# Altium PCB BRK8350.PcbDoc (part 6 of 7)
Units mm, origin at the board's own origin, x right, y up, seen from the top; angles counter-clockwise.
Board outline 240 x 150 mm, 8 copper layers (L1-TOP, L2-GND, L3-PWR, L4-SIG, L5-SIG, L6-PWR, L7-GND, L8-BOT), stack 1.465 mm thick; 277 components, 542 nets, 1814 pads, 2338 vias.
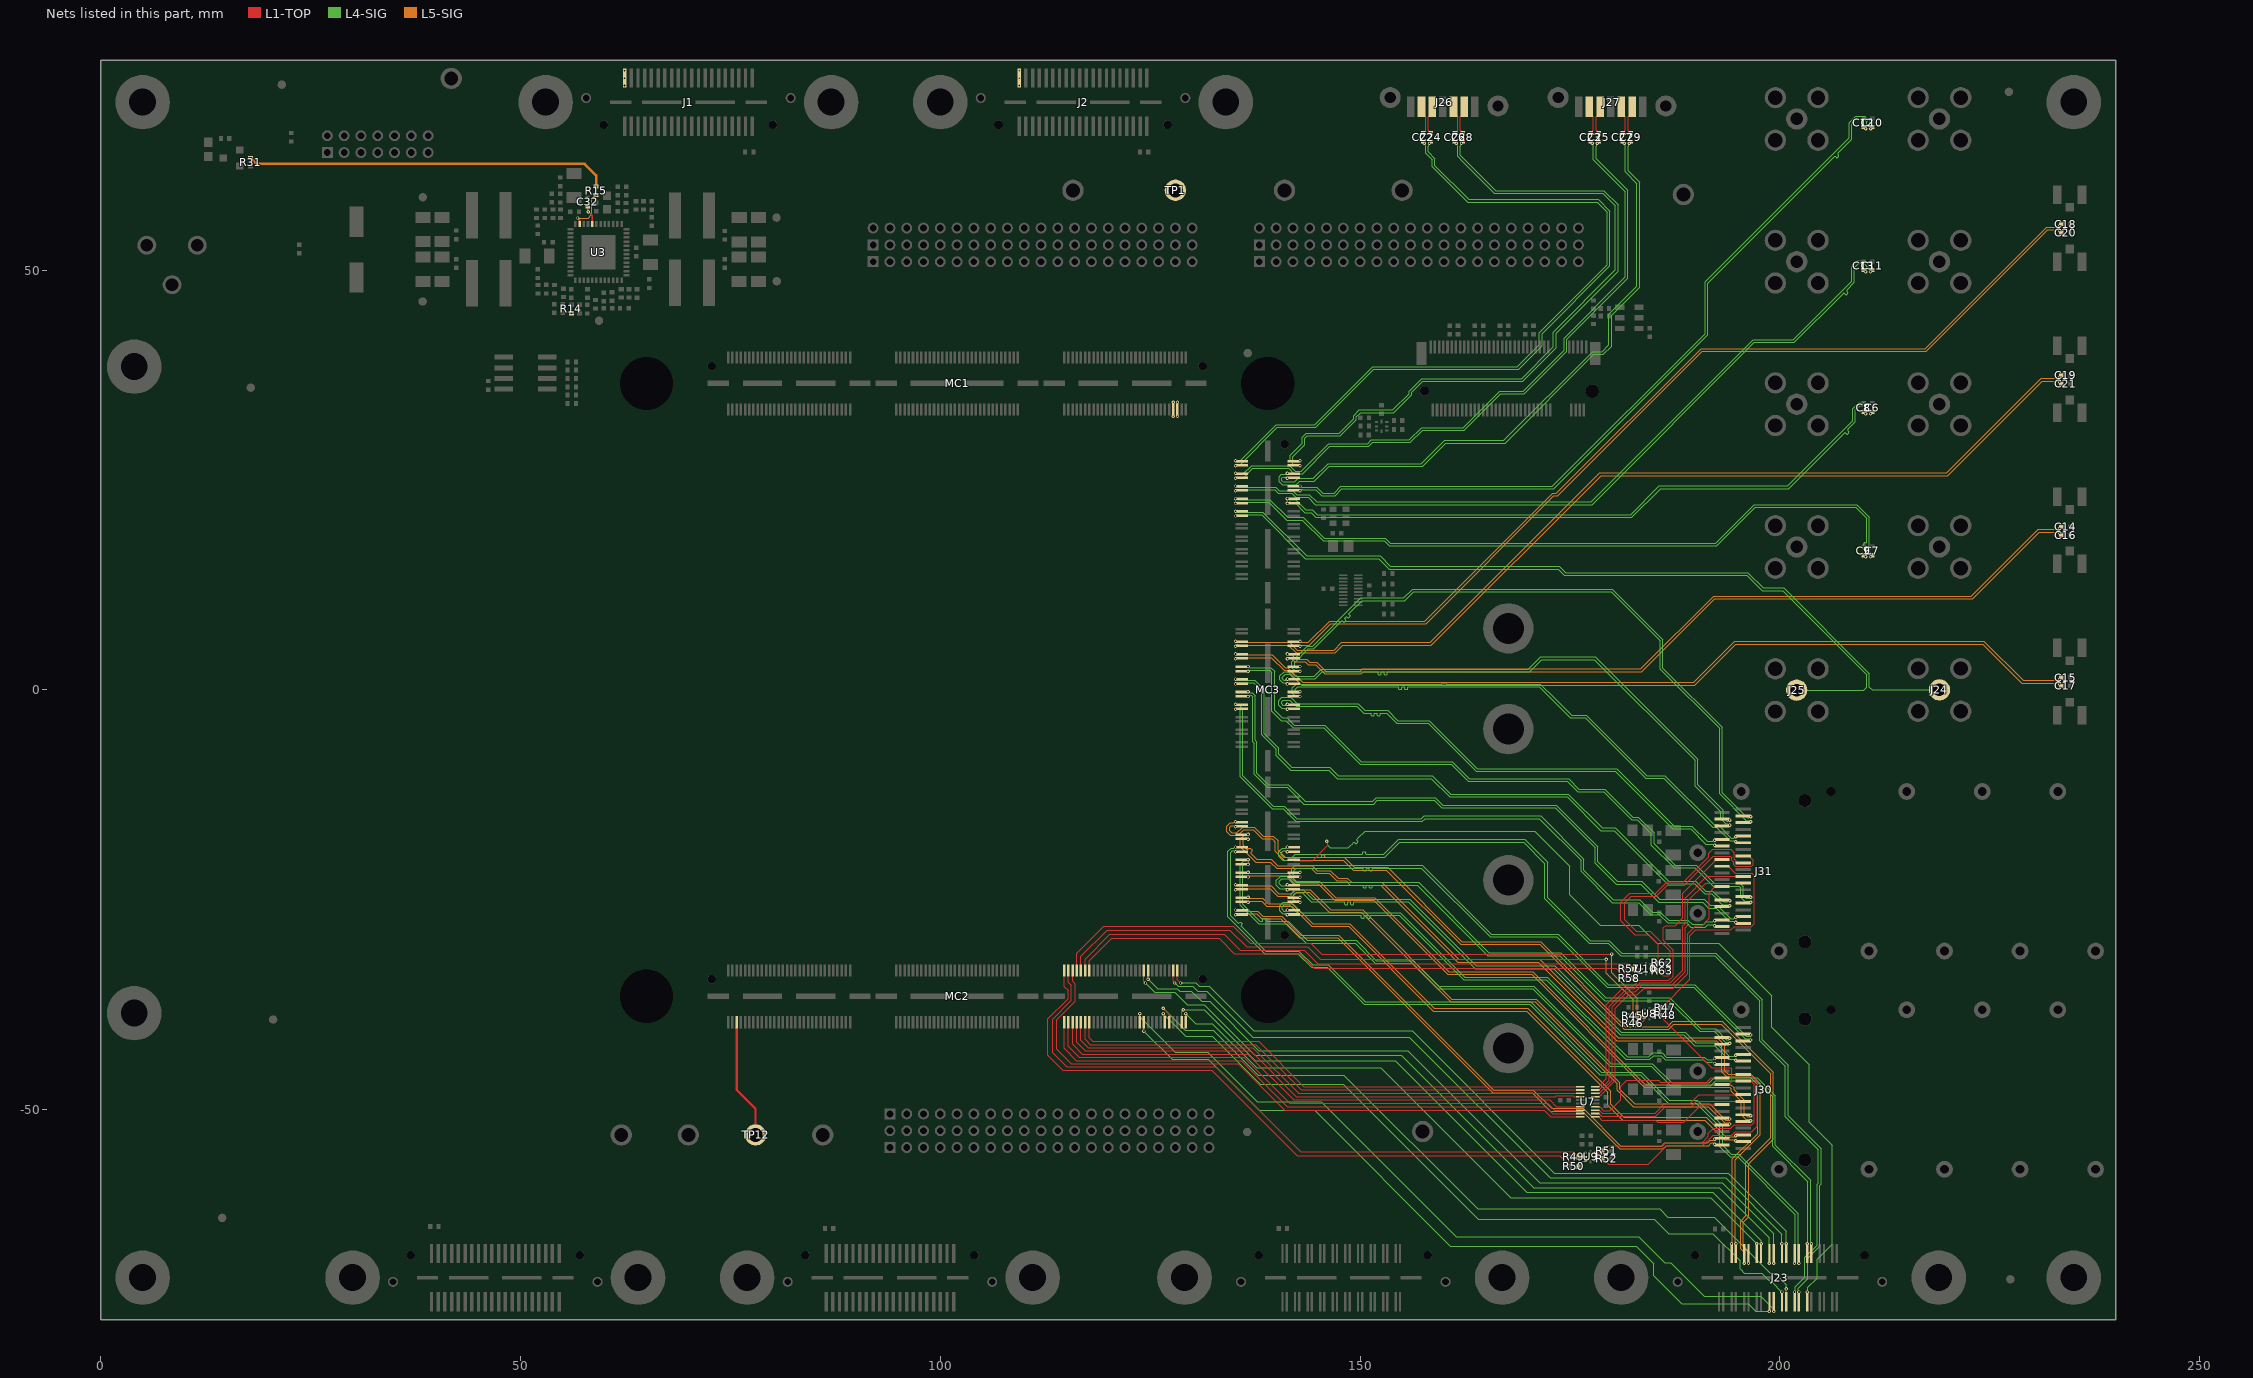
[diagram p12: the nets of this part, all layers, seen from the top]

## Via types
v1: diameter 0.406, hole 0.203, L1-TOP to L8-BOT, tented both sides, 2338 vias

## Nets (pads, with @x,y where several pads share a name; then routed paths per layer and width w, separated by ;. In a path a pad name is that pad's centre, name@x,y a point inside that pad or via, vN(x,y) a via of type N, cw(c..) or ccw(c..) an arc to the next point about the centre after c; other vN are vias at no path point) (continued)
PORTF_RX2P: J23.29 MC3.101 | length 110
  L1-TOP w0.107: MC3.101@142.09,-20.25 142.18,-20.34 144.333,-20.34 146.153,-18.52 146.153,-18.218 146.025,-18.09 v1(146.025,-18.009)
  L4-SIG w0.107: v1(146.025,-18.009) 146.025,-18.09 146.153,-18.218 146.153,-18.522 146.452,-18.821 148.59,-18.821 148.91,-18.501 149.038,-18.374 149.254,-18.157 149.331,-18.157 149.487,-18.313 149.563,-18.313 149.742,-18.134 149.742,-18.058 149.586,-17.902 149.586,-17.826 149.784,-17.628 150.597,-16.815 170.79,-16.815 174.955,-20.98 174.955,-24.405 178.582,-28.031 183.2,-28.031 185.318,-30.15 192.714,-30.15 199.019,-36.455 199.019,-40.163 203.515,-44.659 203.515,-51.517 206.223,-54.224 206.223,-65.994 204.429,-67.787 204.429,-70.05 203.34,-71.14 203.34,-71.534 203.237,-71.637 v1(203.237,-71.718)
PORTF_RX3N: J23.27 MC3.99 | length 109.2
  L4-SIG w0.107: v1(141.344,-19.288) 141.263,-19.288 141.135,-19.16 140.843,-19.16 140.614,-19.388 140.614,-19.66 140.894,-19.939 141.914,-19.939 142.262,-19.591 150.114,-19.591 150.24,-19.591 150.294,-19.537 150.294,-19.317 150.348,-19.263 150.601,-19.263 150.655,-19.317 150.655,-19.537 150.709,-19.591 150.901,-19.591 152.803,-19.591 154.579,-17.816 169.601,-17.816 172.329,-20.543 172.329,-24.759 177.44,-29.87 179.68,-29.87 181.153,-31.344 192.375,-31.344 197.917,-36.885 197.917,-41.661 200.965,-44.709 200.965,-50.703 204.894,-54.632 204.894,-58.86 204.739,-59.014 204.739,-66.253 203.291,-67.701 203.291,-70.114 202.16,-71.246 202.16,-71.534 202.263,-71.637 v1(202.263,-71.718)
PORTF_RX3P: J23.25 MC3.97 | length 109.2
  L4-SIG w0.107: v1(141.344,-18.711) 141.263,-18.711 141.135,-18.84 140.71,-18.84 140.294,-19.256 140.294,-19.792 140.761,-20.259 142.047,-20.259 142.395,-19.911 152.936,-19.911 154.711,-18.136 169.469,-18.136 172.009,-20.676 172.009,-24.892 177.307,-30.19 179.547,-30.19 181.02,-31.664 192.242,-31.664 197.597,-37.018 197.597,-41.793 200.645,-44.841 200.645,-50.836 204.574,-54.765 204.574,-58.727 204.419,-58.882 204.419,-66.121 202.971,-67.569 202.971,-69.982 201.84,-71.113 201.84,-71.534 201.737,-71.637 v1(201.737,-71.718)
PORTF_S0: J23.14 MC2.180 | length 80.4
  L1-TOP w0.114: MC2.180@129.25,-39.59 v1(129.25,-38.55)
  L4-SIG w0.117: v1(129.25,-38.55) 130.452,-39.751 132.41,-39.751 137.668,-45.009 152.457,-45.009 167.951,-60.503 191.762,-60.503 v1(197.237,-65.978)
PORTF_S1: J23.16 MC2.178 | length 82.2
  L1-TOP w0.114: MC2.178@128.75,-39.59 128.75,-38.276 v1(128.933,-38.093)
  L4-SIG w0.117: v1(128.933,-38.093) 131.412,-38.093 137.516,-44.196 154.178,-44.196 169.824,-59.842 191.972,-59.842 197.763,-65.633 v1(197.763,-65.978)
PORTF_S2: J23.17 MC2.160 | length 90.2
  L1-TOP w0.114: v1(124.25,-40.629) MC2.160@124.25,-39.59
  L4-SIG w0.117: v1(124.25,-40.629) 127.614,-43.993 131.902,-43.993 137.973,-50.063 144.577,-50.063 160.757,-66.243 182.883,-66.243 184.988,-68.349 184.988,-69.774 188.316,-73.101 196.201,-73.101 197.122,-74.023 v1(198.737,-74.023)
PORTF_S3: J23.18 MC2.159 | length 91.5
  L1-TOP w0.114: MC2.159@124.25,-33.41 124.25,-34.724 v1(124.433,-34.907)
  L4-SIG w0.117: v1(124.433,-34.907) 125.544,-36.017 127.914,-36.017 129.388,-37.49 131.445,-37.49 137.465,-43.51 154.915,-43.51 170.688,-59.284 192.785,-59.284 198.737,-65.236 v1(198.737,-68.283)
PORTF_S4: J23.19 MC2.158 | length 91.6
  L1-TOP w0.114: MC2.158@123.75,-39.59 v1(123.75,-38.55)
  L4-SIG w0.117: v1(123.75,-38.55) 123.75,-38.914 127.991,-43.155 131.851,-43.155 137.77,-49.073 145.39,-49.073 161.442,-65.126 183.185,-65.126 186.285,-68.226 186.996,-68.226 191.008,-72.238 197.745,-72.238 199.263,-73.755 v1(199.263,-74.023)
PORTF_S5: J23.20 MC2.161 | length 91.6
  L1-TOP w0.114: v1(124.75,-34.449) MC2.161@124.75,-33.41
  L4-SIG w0.117: v1(124.75,-34.449) 125.886,-35.585 128.232,-35.585 128.511,-35.865 129.87,-35.865 131.115,-37.109 132.105,-37.109 137.947,-42.951 155.651,-42.951 171.374,-58.674 193.14,-58.674 199.263,-64.796 v1(199.263,-68.283)
PORTF_S6: J23.21 MC2.170 | length 89.1
  L1-TOP w0.114: v1(126.563,-38.548) 126.75,-38.735 MC2.170@126.75,-39.59
  L4-SIG w0.117: v1(126.563,-38.548) 129.239,-41.224 132.385,-41.224 138.1,-46.939 147.98,-46.939 164.059,-63.017 185.014,-63.017 186.741,-64.745 191.999,-64.745 195.25,-67.996 195.25,-68.961 195.767,-69.478 197.809,-69.478 198.84,-70.509 199.029,-70.509 v1(200.237,-71.718)
PORTF_S7: J23.22 MC2.173 | length 87.4
  L1-TOP w0.114: MC2.173@127.75,-33.41 127.75,-34.724 v1(127.933,-34.907)
  L4-SIG w0.117: v1(127.933,-34.907) 128.333,-35.306 130.048,-35.306 130.645,-35.903 131.737,-35.903 137.185,-41.351 155.88,-41.351 172.618,-58.09 193.523,-58.09 200.237,-64.804 v1(200.237,-65.978)
PORTF_S8: J23.23 MC2.172 | length 91.8
  L1-TOP w0.114: v1(126.563,-37.922) 127.25,-38.609 MC2.172@127.25,-39.59 ; J23.23@200.75,-72.87 200.75,-71.359 v1(200.767,-71.342)
  L4-SIG w0.117: v1(126.563,-37.922) 129.154,-40.513 132.537,-40.513 137.897,-45.872 148.057,-45.872 164.008,-61.824 185.674,-61.824 186.639,-62.789 192.151,-62.789 198.84,-69.478 199.376,-69.478 200.767,-70.869 v1(200.767,-71.342)
PORTF_S9: J23.24 MC2.175 | length 87.5
  L1-TOP w0.114: MC2.175@128.25,-33.41 128.25,-34.536 v1(128.621,-34.907)
  L4-SIG w0.117: v1(128.621,-34.907) 130.436,-34.907 130.835,-35.306 132.029,-35.306 137.338,-40.615 156.185,-40.615 173.152,-57.582 193.853,-57.582 200.763,-64.492 v1(200.763,-65.978)
PORTF_TX0N: J23.8 MC3.96 | length 97.4
  L5-SIG w0.107: v1(136.656,-17.788) ccw(c136.347,-18.097) 136.347,-17.66 136.314,-17.66 136.06,-17.914 136.06,-18.528 136.376,-18.845 136.491,-18.959 136.643,-18.959 136.767,-18.834 136.92,-18.834 137.148,-19.063 137.148,-19.215 137.024,-19.34 137.024,-19.492 137.303,-19.771 137.719,-20.187 139.44,-20.187 140.183,-20.93 144.293,-20.93 144.893,-21.53 146.468,-21.53 147.369,-22.431 148.486,-22.431 148.977,-22.921 152.583,-22.921 161.768,-32.106 171.369,-32.106 180.716,-41.453 192.553,-41.453 193.421,-42.321 193.421,-45.369 193.827,-45.775 196.545,-45.775 197.66,-46.89 197.66,-52.987 194.66,-55.987 194.66,-65.73 ccw(c195.01,-65.73) v1(194.763,-65.978)
PORTF_TX0P: J23.6 MC3.94 | length 97.4
  L5-SIG w0.107: v1(136.656,-17.212) cw(c136.347,-16.902) 136.347,-17.34 136.182,-17.34 135.74,-17.781 135.74,-18.661 137.586,-20.507 139.307,-20.507 140.05,-21.25 144.16,-21.25 144.76,-21.85 146.335,-21.85 147.236,-22.751 148.354,-22.751 148.844,-23.241 152.451,-23.241 161.635,-32.426 171.237,-32.426 180.584,-41.773 192.42,-41.773 193.101,-42.454 193.101,-45.502 193.695,-46.095 196.413,-46.095 197.34,-47.023 197.34,-52.855 194.34,-55.855 194.34,-65.73 cw(c193.989,-65.73) v1(194.237,-65.978)
PORTF_TX1N: J23.12 MC3.92 | length 104.6
  L5-SIG w0.107: v1@135.156,-16.28 v1(135.164,-16.288) 135.083,-16.288 134.955,-16.16 134.661,-16.16 134.457,-16.363 134.457,-16.784 134.685,-17.012 135.332,-17.012 136.006,-16.338 137.413,-16.338 138.48,-17.404 139.649,-17.404 140.235,-17.991 140.235,-19.082 141.101,-19.948 145.237,-19.948 145.363,-19.948 145.418,-19.894 145.418,-19.674 145.472,-19.62 145.724,-19.62 145.778,-19.674 145.778,-19.894 145.832,-19.948 146.075,-19.948 148.137,-19.948 149.322,-21.133 153.264,-21.133 162.131,-30 171.499,-30 181.59,-40.091 186.634,-40.091 187.243,-39.482 193.12,-39.482 199.202,-45.563 199.202,-53.498 196.263,-56.437 196.263,-62.766 195.63,-63.399 195.63,-66.397 196.16,-66.926 196.16,-68.035 ccw(c196.51,-68.035) v1(196.263,-68.283)
PORTF_TX1P: J23.10 MC3.90 | length 104.6
  L5-SIG w0.107: v1@135.156,-15.719 v1(135.164,-15.711) 135.083,-15.711 134.955,-15.84 134.528,-15.84 134.137,-16.231 134.137,-16.917 134.552,-17.332 135.464,-17.332 136.138,-16.658 137.281,-16.658 138.348,-17.724 139.516,-17.724 139.915,-18.124 139.915,-19.214 140.969,-20.268 148.005,-20.268 149.189,-21.453 153.131,-21.453 161.998,-30.32 171.366,-30.32 181.458,-40.411 186.766,-40.411 187.376,-39.802 192.988,-39.802 198.882,-45.696 198.882,-53.365 195.943,-56.304 195.943,-62.633 195.31,-63.266 195.31,-66.529 195.84,-67.059 195.84,-68.035 cw(c195.489,-68.035) v1(195.737,-68.283)
PORTF_TX2N: J23.32 MC3.104 | length 98.7
  L4-SIG w0.107: v1(136.656,-20.788) 136.575,-20.788 136.447,-20.66 136.296,-20.66 136.017,-20.939 136.017,-25.502 138.049,-27.534 138.252,-27.534 138.378,-27.534 138.433,-27.479 138.433,-27.259 138.487,-27.205 138.739,-27.205 138.793,-27.259 138.793,-27.479 138.847,-27.534 139.154,-27.534 139.497,-27.534 141.423,-27.534 143.734,-29.845 149.525,-29.845 151.938,-32.258 156.337,-32.258 159.37,-35.291 170.698,-35.291 179.916,-44.509 184.818,-44.509 187.107,-46.797 191.612,-46.797 192.196,-46.213 197.313,-46.213 199.441,-48.341 199.441,-54.208 203.66,-58.427 203.66,-65.794 203.763,-65.897 v1(203.763,-65.978)
PORTF_TX2P: J23.30 MC3.102 | length 98.7
  L4-SIG w0.107: v1(136.656,-20.212) 136.575,-20.212 136.447,-20.34 136.164,-20.34 135.697,-20.806 135.697,-25.634 137.916,-27.854 141.29,-27.854 143.601,-30.165 149.393,-30.165 151.806,-32.578 156.204,-32.578 159.237,-35.611 170.566,-35.611 179.783,-44.829 184.686,-44.829 186.974,-47.117 191.745,-47.117 192.329,-46.533 197.18,-46.533 199.121,-48.473 199.121,-54.341 203.34,-58.56 203.34,-65.794 203.237,-65.897 v1(203.237,-65.978)
PORTF_TX3N: J23.28 MC3.100 | length 98.4
  L4-SIG w0.107: v1(135.164,-19.288) 135.083,-19.288 134.955,-19.16 134.798,-19.16 134.584,-19.373 134.584,-26.903 135.4,-27.719 135.489,-27.808 135.566,-27.808 135.722,-27.652 135.798,-27.652 135.977,-27.831 135.977,-27.907 135.821,-28.063 135.821,-28.139 135.997,-28.315 138.781,-31.1 142.707,-31.1 144.348,-32.741 146.228,-32.741 150.632,-37.145 170.317,-37.145 178.699,-45.527 183.47,-45.527 186.823,-48.88 190.15,-48.88 193.167,-51.897 193.167,-54.254 194.203,-55.291 195.088,-55.291 202.16,-62.363 202.16,-68.099 202.263,-68.202 v1(202.263,-68.283)
PORTF_TX3P: J23.26 MC3.98 | length 98.4
  L4-SIG w0.107: v1(135.164,-18.712) 135.083,-18.712 134.955,-18.84 134.665,-18.84 134.264,-19.24 134.264,-27.035 138.649,-31.42 142.575,-31.42 144.216,-33.061 146.095,-33.061 150.5,-37.465 170.185,-37.465 178.567,-45.847 183.337,-45.847 186.69,-49.2 190.017,-49.2 192.847,-52.029 192.847,-54.387 194.071,-55.611 194.955,-55.611 201.84,-62.495 201.84,-68.099 201.737,-68.202 v1(201.737,-68.283)
QSFP_1_INT_B: MC2.129 R46.1 U8.3 | length 77.4
  L1-TOP w0.127: MC2.129@116.75,-33.41 116.75,-31.733 119.858,-28.626 134.493,-28.626 136.474,-30.607 143.758,-30.607 145.25,-32.099 v1(179.316,-32.099) ; v1(182.979,-39.694) 183.488,-39.694 183.842,-39.34 U8.3@183.842,-39.051
  L5-SIG w0.127: v1(179.316,-32.099) 179.316,-33.725 182.517,-36.925 182.517,-39.281 182.929,-39.694 v1(182.979,-39.694)
QSFP_1_INT_B_3V3: J30.28 R48.1 U8.6 | length 14.9
  L1-TOP w0.127: U8.6@185.052,-38.551 185.705,-38.551 185.908,-38.754 186.251,-39.096 186.251,-39.364 191.889,-45.003 194.125,-45.003 194.277,-45.155 194.277,-46.628 193.905,-47 J30.28@193.12,-47
QSFP_1_LP_MODE: MC2.125 U7.10 | length 76.1
  L1-TOP w0.127: MC2.125@115.75,-33.41 115.75,-34.699 116.078,-35.027 116.078,-37.084 113.868,-39.294 113.868,-42.799 115.589,-44.52 135.476,-44.52 141.039,-50.083 171.95,-50.083 172.718,-50.851 U7.10@176.208,-50.851
QSFP_1_LP_MODE_3V3: J30.31 U7.11 | length 16.2
  L1-TOP w0.127: U7.11@178.008,-50.851 178.411,-50.851 178.786,-51.226 185.209,-51.226 185.463,-51.48 188.562,-51.48 190.642,-49.4 J30.31@193.12,-49.4
QSFP_1_MODPRS_B: MC2.126 U7.7 | length 66.1
  L1-TOP w0.127: MC2.126@115.75,-39.59 115.75,-42.192 116.935,-43.377 136.619,-43.377 142.08,-48.838 172.56,-48.838 173.373,-49.651 U7.7@176.208,-49.651
QSFP_1_MODPRS_B_3V3: J30.27 U7.14 | length 18.1
  L1-TOP w0.127: U7.14@178.008,-49.651 178.605,-49.651 178.771,-49.816 178.771,-49.905 178.974,-50.108 179.748,-50.108 181.018,-48.838 181.018,-47.212 181.755,-46.476 185.539,-46.476 185.768,-46.704 191.29,-46.704 191.794,-46.2 J30.27@193.12,-46.2
QSFP_1_MODSEL_B: MC2.122 U7.9 | length 67.8
  L1-TOP w0.127: MC2.122@114.75,-39.59 114.75,-42.675 116.214,-44.139 135.832,-44.139 141.343,-49.651 172.154,-49.651 172.953,-50.451 U7.9@176.208,-50.451
QSFP_1_MODSEL_B_3V3: J30.8 U7.12 | length 18.5
  L1-TOP w0.127: U7.12@178.008,-50.451 178.477,-50.451 178.795,-50.768 185.209,-50.768 186.352,-49.625 189.426,-49.625 190.051,-49 J30.8@195.63,-49
QSFP_1_RESET_B: MC2.124 U7.8 | length 67
  L1-TOP w0.127: MC2.124@115.25,-39.59 115.25,-42.429 116.58,-43.758 136.162,-43.758 141.623,-49.219 172.331,-49.219 173.163,-50.051 U7.8@176.208,-50.051
QSFP_1_RESET_B_3V3: J30.9 U7.13 | length 18.7
  L1-TOP w0.127: U7.13@178.008,-50.051 178.482,-50.051 178.844,-50.413 185.133,-50.413 186.301,-49.244 189.299,-49.244 190.343,-48.2 J30.9@195.63,-48.2
QSFP_1_RX1N: J30.18 MC3.107 | length 65.1
  L4-SIG w0.107: v1(142.836,-22.288) 142.755,-22.288 142.627,-22.16 142.154,-22.16 141.834,-21.84 141.834,-21.326 142.255,-20.904 157.429,-20.904 165.633,-29.108 173.582,-29.108 179.581,-35.107 189.864,-35.107 195.996,-41.239 196.397,-41.239 v1(196.531,-41.104)
QSFP_1_RX1P: J30.17 MC3.105 | length 65.1
  L4-SIG w0.107: v1(142.836,-21.711) 142.755,-21.711 142.627,-21.84 142.286,-21.84 142.154,-21.707 142.154,-21.458 142.388,-21.224 149.842,-21.224 150.023,-21.224 150.329,-21.224 150.383,-21.278 150.383,-21.498 150.437,-21.552 150.69,-21.552 150.744,-21.498 150.744,-21.278 150.798,-21.224 151.05,-21.224 151.105,-21.278 151.105,-21.498 151.159,-21.552 151.411,-21.552 151.465,-21.498 151.465,-21.278 151.519,-21.224 151.917,-21.224 157.297,-21.224 165.501,-29.428 173.45,-29.428 179.448,-35.427 189.732,-35.427 195.864,-41.559 196.394,-41.559 v1(196.531,-41.696)
QSFP_1_RX2N: J30.21 MC3.111 | length 64.4
  L4-SIG w0.107: v1(141.344,-23.788) ccw(c141.035,-24.097) 141.035,-23.66 140.453,-23.66 140.04,-23.247 140.04,-22.669 140.525,-22.184 141.568,-22.184 142.32,-22.936 156.967,-22.936 165.349,-31.318 173.887,-31.318 179.25,-36.682 186.896,-36.682 190.56,-40.345 192.34,-40.345 193.635,-41.64 193.885,-41.64 v1(194.021,-41.504)
QSFP_1_RX2P: J30.22 MC3.109 | length 64.4
  L4-SIG w0.107: v1(141.344,-23.211) cw(c141.035,-22.902) 141.035,-23.34 140.586,-23.34 140.36,-23.114 140.36,-22.802 140.658,-22.504 141.435,-22.504 142.187,-23.256 149.835,-23.256 150.015,-23.256 150.322,-23.256 150.376,-23.31 150.376,-23.531 150.43,-23.585 150.682,-23.585 150.736,-23.531 150.736,-23.31 150.79,-23.256 151.043,-23.256 151.097,-23.31 151.097,-23.531 151.151,-23.585 151.404,-23.585 151.458,-23.531 151.458,-23.31 151.512,-23.256 151.79,-23.256 156.835,-23.256 165.217,-31.638 173.754,-31.638 179.118,-37.002 186.763,-37.002 190.427,-40.665 192.207,-40.665 193.502,-41.96 193.885,-41.96 v1(194.021,-42.096)
QSFP_1_RX3N: J30.15 MC3.115 | length 63.1
  L4-SIG w0.107: v1(142.836,-25.288) ccw(c142.527,-25.597) 142.527,-25.16 142.257,-25.16 141.785,-24.688 141.785,-24.249 142.224,-23.81 143.215,-23.81 144.342,-24.937 155.893,-24.937 163.824,-32.868 173.198,-32.868 181.097,-40.767 188.697,-40.767 189.967,-42.037 192.354,-42.037 193.957,-43.64 194.594,-43.64 v1(194.73,-43.504)
QSFP_1_RX3P: J30.14 MC3.113 | length 63.1
  L4-SIG w0.107: v1(142.836,-24.711) cw(c142.527,-24.402) 142.527,-24.84 142.389,-24.84 142.105,-24.556 142.105,-24.382 142.357,-24.13 143.083,-24.13 144.209,-25.257 147.625,-25.257 147.805,-25.257 148.112,-25.257 148.166,-25.311 148.166,-25.531 148.22,-25.585 148.472,-25.585 148.526,-25.531 148.526,-25.311 148.581,-25.257 148.833,-25.257 148.887,-25.311 148.887,-25.531 148.941,-25.585 149.194,-25.585 149.248,-25.531 149.248,-25.311 149.302,-25.257 149.504,-25.257 155.76,-25.257 163.691,-33.188 173.065,-33.188 180.965,-41.087 188.564,-41.087 189.834,-42.357 192.222,-42.357 193.825,-43.96 194.594,-43.96 v1(194.73,-44.096)
QSFP_1_RX4N: J30.24 MC3.119 | length 61.8
  L4-SIG w0.107: v1(141.344,-26.788) ccw(c141.035,-27.097) 141.035,-26.66 140.785,-26.66 140.404,-26.278 140.404,-25.717 140.839,-25.282 141.709,-25.282 142.08,-25.652 ; 142.103,-25.675 142.964,-26.537 154.802,-26.537 162.479,-34.214 172.314,-34.214 181.788,-43.688 184.379,-43.688 184.826,-43.241 185.984,-43.241 186.467,-43.724 191.017,-43.724 191.333,-44.04 191.892,-44.04 ccw(c191.892,-43.576) v1(192.22,-43.904)
QSFP_1_RX4P: J30.25 MC3.117 | length 61.9
  L4-SIG w0.107: v1(141.344,-26.211) cw(c141.035,-25.902) 141.035,-26.34 140.918,-26.34 140.724,-26.146 140.724,-25.85 140.971,-25.602 141.577,-25.602 142.832,-26.857 149.581,-26.857 149.761,-26.857 150.068,-26.857 150.122,-26.911 150.122,-27.131 150.176,-27.185 150.428,-27.185 150.482,-27.131 150.482,-26.911 150.536,-26.857 150.789,-26.857 150.843,-26.911 150.843,-27.131 150.897,-27.185 151.15,-27.185 151.204,-27.131 151.204,-26.911 151.258,-26.857 151.663,-26.857 154.67,-26.857 162.347,-34.534 172.181,-34.534 181.655,-44.008 184.511,-44.008 184.958,-43.561 185.852,-43.561 186.334,-44.044 190.884,-44.044 191.201,-44.36 191.892,-44.36 cw(c191.892,-44.824) v1(192.22,-44.496)
QSFP_1_SCL: MC2.123 R49.1 U9.2 | length 79.5
  L1-TOP w0.127: MC2.123@115.25,-33.41 115.25,-34.826 115.621,-35.196 115.621,-36.982 113.386,-39.218 113.386,-43.231 115.056,-44.901 132.809,-44.901 142.918,-55.01 175.397,-55.01 175.92,-55.534 175.92,-55.626 175.927,-55.62 U9.2@176.836,-55.62
QSFP_1_SCL_3V3: J30.11 R51.1 U9.7 | length 26.6
  L1-TOP w0.127: U9.7@178.046,-55.12 178.724,-55.12 178.929,-54.915 179.57,-54.274 186.047,-54.274 186.352,-53.969 190.67,-53.969 191.483,-53.156 191.483,-52.826 192.118,-52.191 194.125,-52.191 194.531,-51.784 196.665,-51.784 196.969,-51.48 196.969,-46.958 196.611,-46.6 J30.11@195.63,-46.6
QSFP_1_SDA: MC2.121 R50.1 U9.3 | length 81.1
  L1-TOP w0.127: MC2.121@114.75,-33.41 114.75,-35.325 115.214,-35.789 115.214,-36.779 112.801,-39.192 112.801,-43.499 114.585,-45.282 132.326,-45.282 142.537,-55.493 173.754,-55.493 174.44,-56.179 175.405,-56.179 175.92,-56.694 175.92,-56.744 176.544,-56.12 U9.3@176.836,-56.12
QSFP_1_SDA_3V3: J30.12 R52.1 U9.6 | length 28.8
  L1-TOP w0.127: U9.6@178.046,-55.62 178.719,-55.62 178.929,-55.829 179.608,-56.509 184.295,-56.509 186.555,-54.248 190.797,-54.248 192.033,-53.012 194.243,-53.012 194.655,-52.6 196.662,-52.6 197.274,-51.988 197.274,-46.654 196.421,-45.8 J30.12@195.63,-45.8
QSFP_1_TX1N: J30.37 MC3.120 | length 69
  L5-SIG w0.107: v1(135.164,-26.788) 135.292,-26.66 137.688,-26.66 138.287,-27.259 140.543,-27.259 142.814,-29.53 147.335,-29.53 165.811,-48.006 170.515,-48.006 172.674,-50.165 176.433,-50.165 180.919,-54.651 186.065,-54.651 186.436,-54.28 191.526,-54.28 191.846,-53.96 192.084,-53.96 v1(192.22,-54.096)
QSFP_1_TX1P: J30.36 MC3.118 | length 69
  L5-SIG w0.107: v1(135.164,-26.211) 135.292,-26.34 137.82,-26.34 138.42,-26.939 140.676,-26.939 142.947,-29.21 147.468,-29.21 165.944,-47.686 170.647,-47.686 172.806,-49.845 176.566,-49.845 181.051,-54.331 185.933,-54.331 186.303,-53.96 191.394,-53.96 191.714,-53.64 192.084,-53.64 v1(192.22,-53.504)
QSFP_1_TX2N: J30.2 MC3.116 | length 70.8
  L5-SIG w0.107: v1(136.656,-25.288) 136.784,-25.16 138.296,-25.16 138.907,-25.771 141.853,-25.771 144.241,-28.158 148.631,-28.158 158.725,-38.252 169.824,-38.252 179.512,-47.94 179.512,-49.467 181.277,-51.232 191.063,-51.232 193.392,-53.56 194.594,-53.56 v1(194.73,-53.696)
QSFP_1_TX2P: J30.3 MC3.114 | length 70.8
  L5-SIG w0.107: v1(136.656,-24.711) 136.784,-24.84 138.428,-24.84 139.04,-25.451 141.986,-25.451 144.374,-27.838 148.763,-27.838 158.857,-37.932 169.957,-37.932 179.832,-47.807 179.832,-49.334 181.409,-50.912 191.196,-50.912 193.524,-53.24 194.594,-53.24 v1(194.73,-53.104)
QSFP_1_TX3N: J30.34 MC3.112 | length 71.4
  L5-SIG w0.107: v1(135.164,-23.788) 135.292,-23.66 139.287,-23.66 140.196,-24.569 141.974,-24.569 142.439,-24.105 143.942,-24.105 146.345,-26.507 150.159,-26.507 160.812,-37.16 170.866,-37.16 180.596,-46.891 180.596,-47.673 182.555,-49.632 191.487,-49.632 193.415,-51.56 193.885,-51.56 v1(194.021,-51.696)
QSFP_1_TX3P: J30.33 MC3.110 | length 71.4
  L5-SIG w0.107: v1(135.164,-23.211) 135.292,-23.34 139.419,-23.34 140.329,-24.249 141.841,-24.249 142.306,-23.785 144.074,-23.785 146.477,-26.187 150.292,-26.187 160.945,-36.84 170.998,-36.84 180.916,-46.758 180.916,-47.541 182.687,-49.312 191.62,-49.312 193.548,-51.24 193.885,-51.24 v1(194.021,-51.104)
QSFP_1_TX4N: J30.5 MC3.108 | length 73.1
  L5-SIG w0.107: v1(136.656,-22.288) 136.784,-22.16 141.291,-22.16 142.235,-23.104 145.024,-23.104 146.98,-25.06 151.602,-25.06 160.426,-33.884 170.413,-33.884 183.85,-47.32 194.033,-47.32 194.211,-47.498 194.211,-47.78 195.417,-48.986 195.417,-50.622 195.955,-51.16 196.395,-51.16 v1(196.531,-51.296)
QSFP_1_TX4P: J30.6 MC3.106 | length 73.1
  L5-SIG w0.107: v1(136.656,-21.711) 136.784,-21.84 141.424,-21.84 142.368,-22.784 145.156,-22.784 147.112,-24.74 151.735,-24.74 160.559,-33.564 170.546,-33.564 183.982,-47 194.166,-47 194.531,-47.365 194.531,-47.647 195.737,-48.853 195.737,-50.489 196.088,-50.84 196.395,-50.84 v1(196.531,-50.704)
QSFP_2_INT_B: MC2.127 R45.1 U8.2 | length 78
  L1-TOP w0.127: MC2.127@116.25,-33.41 116.25,-31.349 119.456,-28.143 134.899,-28.143 136.931,-30.175 144.12,-30.175 145.409,-31.464 v1(179.977,-31.464) ; v1(182.979,-38.78) 183.336,-38.78 183.564,-38.551 U8.2@183.842,-38.551
  L5-SIG w0.127: v1(179.977,-31.464) 179.977,-33.7 182.979,-36.702 v1(182.979,-38.78)
QSFP_2_INT_B_3V3: J31.28 R47.1 U8.7 | length 29.2
  L1-TOP w0.127: U8.7@185.052,-38.051 185.697,-38.051 185.908,-37.84 185.908,-37.826 189.248,-34.487 189.248,-29.28 189.959,-28.569 194.15,-28.569 194.531,-28.188 196.598,-28.188 196.944,-27.842 196.944,-22.117 196.639,-21.812 194.658,-21.812 193.846,-21 J31.28@193.12,-21
QSFP_2_LP_MODE: MC2.128 U7.4 | length 65.1
  L1-TOP w0.127: MC2.128@116.25,-39.59 116.25,-41.979 117.272,-43 136.953,-43 142.385,-48.432 173.271,-48.432 173.373,-48.33 175.367,-48.33 175.488,-48.451 U7.4@176.208,-48.451
QSFP_2_LP_MODE_3V3: J31.31 U7.17 | length 35.2
  L1-TOP w0.127: U7.17@178.008,-48.451 178.477,-48.451 180.409,-46.519 180.409,-37.891 182.009,-36.29 183.025,-36.29 183.812,-35.503 187.317,-35.503 188.994,-33.827 188.994,-29.026 189.959,-28.061 190.721,-28.061 191.559,-27.223 191.559,-24.149 192.308,-23.4 J31.31@193.12,-23.4
QSFP_2_MODPRS_B: MC2.134 U7.1 | length 62.7
  L1-TOP w0.127: MC2.134@117.75,-39.59 117.75,-41.443 118.161,-41.853 137.916,-41.853 143.313,-47.251 U7.1@176.208,-47.251
QSFP_2_MODPRS_B_3V3: J31.27 U7.20 | length 39
  L1-TOP w0.127: U7.20@178.008,-47.251 178.403,-47.251 179.316,-46.337 179.316,-37.51 181.602,-35.224 182.618,-35.224 183.253,-34.589 186.784,-34.589 187.292,-34.081 187.292,-30.982 186.098,-29.788 186.098,-28.34 186.378,-28.061 187.521,-28.061 188.435,-27.146 188.435,-24.2 192.435,-20.2 J31.27@193.12,-20.2 J31.27@193.808,-20.2
QSFP_2_MODSEL_B: MC2.130 U7.3 | length 64.2
  L1-TOP w0.127: MC2.130@116.75,-39.59 116.75,-41.744 117.621,-42.615 137.229,-42.615 142.664,-48.051 U7.3@176.208,-48.051
QSFP_2_MODSEL_B_3V3: J31.8 U7.18 | length 37.9
  L1-TOP w0.127: U7.18@178.008,-48.051 178.477,-48.051 180.053,-46.475 180.053,-37.713 181.806,-35.96 182.796,-35.96 183.558,-35.198 187.089,-35.198 188.714,-33.573 188.714,-28.34 189.019,-28.035 189.019,-25.14 191.159,-23 J31.8@195.63,-23
QSFP_2_RESET_B: MC2.132 U7.2 | length 63.5
  L1-TOP w0.127: MC2.132@117.25,-39.59 117.25,-41.635 117.85,-42.234 137.567,-42.234 142.984,-47.651 U7.2@176.208,-47.651
QSFP_2_RESET_B_3V3: J31.9 U7.19 | length 38.2
  L1-TOP w0.127: U7.19@178.008,-47.651 178.482,-47.651 179.672,-46.461 179.672,-37.687 181.755,-35.605 182.669,-35.605 183.38,-34.893 186.911,-34.893 188.435,-33.369 188.435,-28.112 188.714,-27.832 188.714,-24.798 191.312,-22.2 J31.9@195.63,-22.2
QSFP_2_RX1N: J31.18 MC3.55 | length 78
  L4-SIG w0.107: v1(142.836,2.212) 142.755,2.212 142.627,2.34 142.19,2.34 141.869,2.661 141.869,3.358 143.718,5.207 144.348,5.207 150.104,10.963 155.214,10.963 156.255,12.004 180.041,12.004 186.07,5.975 186.07,2.601 193.131,-4.46 193.131,-12.263 196.109,-15.24 196.318,-15.24 196.454,-15.104 v1(196.531,-15.104) v1@196.528,-15.107
QSFP_2_RX1P: J31.17 MC3.53 | length 78
  L4-SIG w0.107: v1(142.836,2.788) 142.755,2.788 142.627,2.66 142.323,2.66 142.189,2.794 142.189,3.226 143.85,4.887 144.481,4.887 147.47,7.876 147.598,8.004 147.814,8.221 147.891,8.221 148.047,8.065 148.123,8.065 148.302,8.243 148.302,8.32 148.146,8.476 148.146,8.552 148.324,8.731 148.401,8.731 148.557,8.575 148.633,8.575 148.812,8.753 148.812,8.83 148.656,8.986 148.656,9.062 148.943,9.349 150.236,10.643 155.346,10.643 156.388,11.684 179.908,11.684 185.75,5.842 185.75,2.468 192.811,-4.593 192.811,-12.395 195.976,-15.56 196.318,-15.56 196.454,-15.696 v1(196.531,-15.696) v1@196.528,-15.693
QSFP_2_RX2N: J31.21 MC3.59 | length 67
  L4-SIG w0.107: v1(141.344,0.712) 141.263,0.712 141.135,0.84 140.795,0.84 140.421,1.214 140.421,1.657 140.939,2.174 141.763,2.174 142.296,1.641 144.516,1.641 145.356,2.481 170.05,2.481 171.495,3.927 178.034,3.927 190.236,-8.275 190.236,-11.318 193.269,-14.351 193.269,-15.236 193.673,-15.64 193.808,-15.64 193.944,-15.504 v1(194.021,-15.504)
QSFP_2_RX2P: J31.22 MC3.57 | length 67
  L4-SIG w0.107: v1(141.344,1.288) 141.263,1.288 141.135,1.16 140.927,1.16 140.741,1.346 140.741,1.524 141.072,1.854 141.63,1.854 142.164,1.321 144.648,1.321 145.489,2.161 151.613,2.161 151.793,2.161 152.1,2.161 152.154,2.107 152.154,1.887 152.208,1.833 152.46,1.833 152.514,1.887 152.514,2.107 152.568,2.161 152.821,2.161 152.875,2.107 152.875,1.887 152.929,1.833 153.182,1.833 153.236,1.887 153.236,2.107 153.29,2.161 153.543,2.161 170.182,2.161 171.628,3.607 177.902,3.607 189.916,-8.407 189.916,-11.451 192.949,-14.484 192.949,-15.368 193.54,-15.96 193.808,-15.96 193.944,-16.096 v1(194.021,-16.096)
QSFP_2_RX3N: J31.15 MC3.63 | length 62.4
  L4-SIG w0.107: v1(142.836,-0.788) 142.755,-0.788 142.627,-0.66 142.209,-0.66 141.945,-0.396 141.945,0.234 142.412,0.701 159.706,0.701 159.709,0.704 160.291,0.704 160.294,0.701 171.481,0.701 173.096,-0.914 175.179,-2.997 176.932,-2.997 184.145,-10.211 186.309,-10.211 192.119,-16.021 192.575,-16.021 194.194,-17.64 194.35,-17.64 194.517,-17.64 194.653,-17.504 v1(194.729,-17.504) v1@194.656,-17.578
QSFP_2_RX3P: J31.14 MC3.61 | length 62.4
  L4-SIG w0.107: v1(142.836,-0.212) 142.755,-0.212 142.627,-0.34 142.342,-0.34 142.265,-0.263 142.265,0.102 142.545,0.381 154.051,0.381 154.231,0.381 154.538,0.381 154.592,0.327 154.592,0.107 154.646,0.052 154.899,0.052 154.953,0.107 154.953,0.327 155.007,0.381 155.259,0.381 155.313,0.327 155.313,0.107 155.367,0.052 155.62,0.052 155.674,0.107 155.674,0.327 155.728,0.381 156.21,0.381 159.839,0.381 159.841,0.384 160.159,0.384 160.161,0.381 171.348,0.381 172.964,-1.234 175.047,-3.317 176.799,-3.317 184.013,-10.531 186.176,-10.531 191.987,-16.341 192.442,-16.341 194.061,-17.96 194.217,-17.96 194.517,-17.96 194.653,-18.096 v1(194.729,-18.096) v1@194.656,-18.022
QSFP_2_RX4N: J31.24 MC3.67 | length 61
  L4-SIG w0.107: v1(141.344,-2.288) 141.263,-2.288 141.135,-2.16 140.67,-2.16 140.32,-1.809 140.32,-1.264 140.685,-0.899 141.763,-0.899 142.515,-1.651 149.754,-1.651 150.551,-2.449 153.295,-2.449 154.504,-3.658 158.263,-3.658 163.978,-9.373 180.539,-9.373 187.397,-16.231 189.508,-16.231 191.317,-18.04 191.641,-18.04 192.007,-18.04 192.143,-17.904 v1(192.219,-17.904) v1@192.167,-17.957
QSFP_2_RX4P: J31.25 MC3.65 | length 61
  L4-SIG w0.107: v1(141.344,-1.712) 141.263,-1.712 141.135,-1.84 140.803,-1.84 140.64,-1.676 140.64,-1.397 140.818,-1.219 141.63,-1.219 142.382,-1.971 149.621,-1.971 150.419,-2.769 150.8,-2.769 150.98,-2.769 151.287,-2.769 151.341,-2.823 151.341,-3.043 151.395,-3.097 151.647,-3.097 151.701,-3.043 151.701,-2.823 151.756,-2.769 152.008,-2.769 152.062,-2.823 152.062,-3.043 152.116,-3.097 152.369,-3.097 152.423,-3.043 152.423,-2.823 152.477,-2.769 152.654,-2.769 153.162,-2.769 154.371,-3.978 158.13,-3.978 163.845,-9.693 180.406,-9.693 187.264,-16.551 189.375,-16.551 191.185,-18.36 191.509,-18.36 192.007,-18.36 192.143,-18.496 v1(192.219,-18.496) v1@192.167,-18.443
QSFP_2_SCL: MC2.131 R57.1 U10.2 | length 70.5
  L1-TOP w0.127: MC2.131@117.25,-33.41 117.25,-32.051 120.193,-29.108 133.831,-29.108 135.736,-31.013 143.332,-31.013 144.952,-32.633 181.983,-32.633 182.484,-33.134 182.484,-33.22 R57.1@182.534,-33.22 183.433,-33.22 U10.2@183.436,-33.217
QSFP_2_SCL_3V3: J31.11 R62.1 U10.7 | length 29.6
  L1-TOP w0.127: U10.7@184.646,-32.717 185.323,-32.717 185.521,-32.519 185.521,-30.278 184.396,-29.153 182.7,-29.153 181.069,-27.522 181.069,-25.296 182.139,-24.225 185.209,-24.225 186.581,-22.854 188.562,-22.854 191.534,-19.882 191.534,-19.45 191.984,-19 194.157,-19 194.531,-19.374 194.531,-20.161 194.97,-20.6 J31.11@195.63,-20.6
QSFP_2_SDA: MC2.133 R58.1 U10.3 | length 70.2
  L1-TOP w0.127: MC2.133@117.75,-33.41 117.75,-32.256 120.415,-29.591 133.198,-29.591 135.001,-31.394 142.748,-31.394 144.52,-33.166 180.51,-33.166 181.12,-33.776 181.983,-33.776 182.484,-34.277 182.484,-34.337 R58.1@182.534,-34.337 182.551,-34.337 183.172,-33.717 U10.3@183.436,-33.717
QSFP_2_SDA_3V3: J31.12 R63.1 U10.6 | length 35.6
  L1-TOP w0.127: U10.6@184.646,-33.217 185.315,-33.217 185.521,-33.423 186.128,-34.03 186.759,-34.03 186.962,-33.827 186.962,-31.134 184.574,-28.747 182.876,-28.747 181.526,-27.397 181.526,-25.343 182.269,-24.6 185.241,-24.6 186.591,-23.25 188.611,-23.25 192.054,-19.806 194.099,-19.806 194.277,-19.984 194.277,-20.288 194.506,-20.517 194.506,-20.847 194.658,-21 196.614,-21 196.817,-20.796 196.817,-20.263 196.354,-19.8 J31.12@195.63,-19.8 J31.12@194.906,-19.8
QSFP_2_TX1N: J31.37 MC3.68 | length 73.9
  L4-SIG w0.107: v1(135.164,-2.288) 135.246,-2.288 135.374,-2.16 135.474,-2.16 135.722,-2.408 135.722,-10.343 139.552,-14.173 140.843,-14.173 142.331,-15.662 157.409,-15.662 157.755,-15.316 171.353,-15.316 176.337,-20.3 176.337,-21.621 180.04,-25.324 183.189,-25.324 184.637,-26.772 185.626,-26.772 186.611,-27.756 188.919,-27.756 189.408,-28.245 191.096,-28.245 191.381,-27.96 192.007,-27.96 192.143,-28.096 v1(192.219,-28.096) v1@192.167,-28.043
QSFP_2_TX1P: J31.36 MC3.66 | length 73.9
  L4-SIG w0.107: v1(135.164,-1.712) 135.246,-1.712 135.374,-1.84 135.606,-1.84 136.042,-2.276 136.042,-10.211 139.685,-13.853 140.976,-13.853 142.464,-15.342 157.277,-15.342 157.622,-14.996 171.486,-14.996 176.657,-20.168 176.657,-21.488 180.172,-25.004 183.322,-25.004 184.77,-26.452 185.759,-26.452 186.743,-27.436 189.052,-27.436 189.54,-27.925 190.963,-27.925 191.248,-27.64 192.007,-27.64 192.143,-27.504 v1(192.219,-27.504) v1@192.166,-27.557
QSFP_2_TX2N: J31.2 MC3.64 | length 76.1
  L4-SIG w0.107: v1(136.656,-0.788) 136.738,-0.788 136.866,-0.66 137.037,-0.66 137.196,-0.818 137.196,-6.152 137.399,-6.355 137.399,-10.043 138.953,-11.598 141.315,-11.598 143.307,-13.589 151.633,-13.589 152.065,-13.157 158.801,-13.157 159.705,-14.061 173.243,-14.061 177.978,-18.796 177.978,-20.62 180.491,-23.133 183.433,-23.133 185.572,-25.273 190.838,-25.273 191.549,-25.984 192.408,-25.984 193.984,-27.56 194.517,-27.56 194.653,-27.696 v1(194.729,-27.696) v1@194.691,-27.658
QSFP_2_TX2P: J31.3 MC3.62 | length 76.1
  L4-SIG w0.107: v1(136.656,-0.212) 136.738,-0.212 136.866,-0.34 137.169,-0.34 137.516,-0.686 137.516,-6.02 137.719,-6.223 137.719,-9.91 139.086,-11.278 141.448,-11.278 143.439,-13.269 151.501,-13.269 151.933,-12.837 158.933,-12.837 159.838,-13.741 173.376,-13.741 178.298,-18.663 178.298,-20.488 180.623,-22.813 183.565,-22.813 185.705,-24.953 190.971,-24.953 191.682,-25.664 192.541,-25.664 194.117,-27.24 194.517,-27.24 194.653,-27.104 v1(194.729,-27.104) v1@194.691,-27.142
QSFP_2_TX3N: J31.34 MC3.60 | length 73.4
  L4-SIG w0.107: v1(135.164,0.712) 135.246,0.712 135.374,0.84 137.336,0.84 138.278,-0.102 138.278,-5.355 140.005,-7.082 140.005,-7.819 141.726,-9.54 146.268,-9.54 147.284,-10.556 158.486,-10.556 160.68,-12.751 174.68,-12.751 178.683,-16.754 180.279,-16.754 186.608,-23.082 189.833,-23.082 191.033,-24.282 191.877,-24.282 193.155,-25.56 193.808,-25.56 193.944,-25.696 v1(194.021,-25.696)
QSFP_2_TX3P: J31.33 MC3.58 | length 73.4
  L4-SIG w0.107: v1(135.164,1.288) 135.246,1.288 135.374,1.16 137.468,1.16 138.598,0.031 138.598,-5.222 140.325,-6.949 140.325,-7.686 141.859,-9.22 146.401,-9.22 147.417,-10.236 158.618,-10.236 160.813,-12.431 174.813,-12.431 178.816,-16.434 180.412,-16.434 186.74,-22.762 189.966,-22.762 191.166,-23.962 192.01,-23.962 193.287,-25.24 193.808,-25.24 193.944,-25.104 v1(194.021,-25.104)
QSFP_2_TX4N: J31.5 MC3.56 | length 75.5
  L4-SIG w0.107: v1(136.656,2.212) 136.738,2.212 136.866,2.34 139.223,2.34 139.497,2.066 139.497,-2.565 140.589,-3.658 141.166,-3.658 142.038,-4.53 145.653,-4.53 150.002,-8.88 160.848,-8.88 162.855,-10.886 174.691,-10.886 175.936,-12.131 179.009,-12.131 182.336,-15.458 183.022,-15.458 184.701,-17.137 184.701,-18.483 187.416,-21.199 189.883,-21.199 192.046,-23.362 195.142,-23.362 195.329,-23.548 195.329,-24.687 195.802,-25.16 196.318,-25.16 196.454,-25.296 v1(196.531,-25.296)
QSFP_2_TX4P: J31.6 MC3.54 | length 75.5
  L4-SIG w0.107: v1(136.656,2.788) 136.738,2.788 136.866,2.66 139.355,2.66 139.817,2.199 139.817,-2.433 140.722,-3.338 141.298,-3.338 142.171,-4.21 145.785,-4.21 150.135,-8.56 160.981,-8.56 162.987,-10.566 174.824,-10.566 176.068,-11.811 179.142,-11.811 182.469,-15.138 183.155,-15.138 185.021,-17.004 185.021,-18.35 187.549,-20.879 190.016,-20.879 192.179,-23.042 195.275,-23.042 195.649,-23.416 195.649,-24.554 195.934,-24.84 196.318,-24.84 196.454,-24.704 v1(196.531,-24.704)
RXN0: C16.2 MC3.51 | length 99.8
  L5-SIG w0.107: v1(141.344,3.712) 141.426,3.712 141.554,3.84 141.732,3.84 142.234,3.338 143.493,3.338 143.848,2.982 144.724,2.982 145.79,1.915 150.153,1.915 150.414,2.175 183.564,2.175 192.234,10.846 222.947,10.846 230.887,18.786 232.997,18.786 cw(c232.997,18.33) v1(233.319,18.652)
RXN1: C20.2 MC3.47 | length 111.1
  L5-SIG w0.107: v1(142.836,5.212) 142.964,5.34 143.969,5.34 146.503,7.874 157.849,7.874 173.078,23.104 173.522,23.104 190.735,40.316 217.416,40.316 231.912,54.811 232.997,54.811 cw(c232.997,54.356) v1(233.319,54.678)
RXN2: C8.2 MC3.15 | length 77.4
  L4-SIG w0.107: v1(141.344,22.212) cw(c141.654,21.903) 141.654,22.34 142.199,22.34 143.42,21.12 144.162,21.12 144.743,20.54 182.345,20.54 185.789,23.984 201.054,23.984 207.407,30.336 207.463,30.393 207.641,30.57 cw(c207.736,30.475) 207.832,30.57 207.909,30.494 ccw(c208.004,30.589) 208.1,30.494 208.182,30.576 ccw(c208.086,30.671) 208.182,30.767 208.105,30.843 cw(c208.201,30.939) 208.105,31.035 208.146,31.076 208.984,31.913 208.984,33.351 209.499,33.867 209.964,33.867 210.333,33.498 210.333,33.219 cw(c209.878,33.219) v1(210.2,32.896)
RXN3: C12.2 MC3.11 | length 92.6
  L4-SIG w0.107: v1(142.836,23.712) cw(c143.146,23.403) 143.146,23.84 144.724,23.84 145.434,23.13 147.032,23.13 147.834,23.933 173.038,23.933 191.414,42.309 191.414,48.456 206.302,63.343 206.442,63.484 cw(c206.538,63.388) 206.633,63.484 206.691,63.426 ccw(c206.786,63.522) 206.882,63.426 206.964,63.508 ccw(c206.868,63.604) 206.964,63.699 206.906,63.757 cw(c207.002,63.852) 206.906,63.948 206.947,63.989 208.559,65.601 208.559,67.437 209.15,68.027 209.969,68.027 210.359,67.638 210.359,67.153 cw(c209.903,67.153) v1(210.225,66.831)
RXP0: C14.2 MC3.49 | length 99.8
  L5-SIG w0.107: v1(141.344,4.289) 141.426,4.289 141.554,4.16 141.864,4.16 142.367,3.658 143.625,3.658 143.981,3.302 144.856,3.302 145.923,2.235 150.021,2.235 150.281,2.495 183.431,2.495 192.102,11.166 222.815,11.166 230.755,19.106 232.997,19.106 ccw(c232.997,19.562) v1(233.319,19.239)
RXP1: C18.2 MC3.45 | length 111.1
  L5-SIG w0.107: v1(142.836,5.788) 142.964,5.66 143.836,5.66 146.37,8.194 157.716,8.194 172.946,23.424 173.39,23.424 190.602,40.636 217.284,40.636 231.779,55.131 232.997,55.131 ccw(c232.997,55.587) v1(233.319,55.265)
RXP2: C6.2 MC3.13 | length 77.5
  L4-SIG w0.107: v1(141.344,22.788) ccw(c141.654,23.098) 141.654,22.66 142.332,22.66 143.552,21.44 144.295,21.44 144.875,20.86 182.212,20.86 185.656,24.304 200.922,24.304 208.664,32.046 208.664,33.484 209.367,34.187 210.097,34.187 210.654,33.63 210.654,33.219 ccw(c211.109,33.219) v1(210.787,32.896)
RXP3: C10.2 MC3.9 | length 92.7
  L4-SIG w0.107: v1(142.836,24.288) ccw(c143.146,24.598) 143.146,24.16 144.856,24.16 145.566,23.45 146.899,23.45 147.702,24.253 172.905,24.253 191.094,42.442 191.094,48.589 208.239,65.734 208.239,67.57 209.017,68.347 210.102,68.347 210.679,67.771 210.679,67.153 ccw(c211.135,67.153) v1(210.812,66.831)
SATA_1_TXA+: C22.2 MC3.2 | length 87.4
  L4-SIG w0.107: v1(135.164,27.289) 135.181,27.272 ccw(c135.451,27.542) 135.451,27.16 135.584,27.16 140.021,31.598 144.595,31.598 151.484,38.487 168.743,38.487 171.351,41.095 171.351,42.557 179.418,50.624 179.418,56.904 178.215,58.106 162.807,58.106 158.598,62.316 158.598,63.137 157.795,63.94 157.795,64.754 ccw(c157.301,64.754) v1(157.65,65.104)
SATA_1_TXA+_C: C22.1 J26.2 | length 3.5
  L1-TOP w0.107: J26.2@157.315,69.45 157.315,68.693 157.79,68.218 157.79,66.621 C22.1@157.447,66.278
SATA_1_TXA-: C24.2 MC3.4 | length 87.9
  L4-SIG w0.107: v1(135.164,26.712) 135.181,26.729 cw(c135.451,26.459) 135.451,26.84 135.716,26.84 140.154,31.278 144.727,31.278 151.617,38.167 168.876,38.167 171.671,40.963 171.671,42.424 179.738,50.491 179.738,57.036 178.348,58.426 162.94,58.426 158.918,62.449 158.918,63.27 158.115,64.072 158.115,64.754 cw(c158.609,64.754) v1(158.26,65.104)
SATA_1_TXA-_C: C24.1 J26.3 | length 3.5
  L1-TOP w0.107: C24.1@158.463,66.278 158.11,66.631 158.11,68.208 158.585,68.683 J26.3@158.585,69.45
SATA_1_TXB+: C28.2 MC3.1 | length 81.8
  L4-SIG w0.107: v1(142.836,27.289) cw(c142.527,27.598) 142.527,27.16 142.226,27.16 141.973,27.414 141.973,27.789 143.406,29.222 143.406,29.965 143.699,30.258 147.652,30.258 149.545,32.151 149.545,32.512 150.053,33.02 154.021,33.02 156.149,35.148 156.149,35.458 157.451,36.76 169.355,36.76 173.337,40.742 173.337,42.481 180.736,49.88 180.736,57.769 179.037,59.468 166.134,59.468 161.929,63.672 161.929,64.745 cw(c162.437,64.745) v1(162.078,65.104)
SATA_1_TXB+_C: C28.1 J26.6 | length 3.5
  L1-TOP w0.107: C28.1@162.281,66.278 161.92,66.638 161.92,68.233 162.395,68.708 J26.6@162.395,69.45
SATA_1_TXB-: C26.2 MC3.3 | length 82.3
  L4-SIG w0.107: v1(142.836,26.712) ccw(c142.527,26.403) 142.527,26.84 142.094,26.84 141.653,27.281 141.653,27.921 143.086,29.354 143.086,30.097 143.567,30.578 147.519,30.578 149.225,32.283 149.225,32.645 149.92,33.34 153.888,33.34 155.829,35.281 155.829,35.591 157.318,37.08 169.222,37.08 173.017,40.875 173.017,42.614 180.416,50.013 180.416,57.636 178.905,59.148 166.001,59.148 162.178,62.971 ; v1(161.46,65.104) cw(c161.101,64.745) 161.609,64.745 161.609,63.54 162.177,62.972
SATA_1_TXB-_C: C26.1 J26.5 | length 3.5
  L1-TOP w0.107: J26.5@161.125,69.45 161.125,68.718 161.6,68.243 161.6,66.621 C26.1@161.257,66.278
SATA_2_TXA+: C23.2 MC3.6 | length 75.1
  L4-SIG w0.107: v1(135.164,25.788) 135.292,25.66 136.042,25.66 137.073,26.691 141.634,26.691 142.259,26.067 143.013,26.067 146.273,29.327 150.891,29.327 151.351,29.786 155.869,29.786 157.314,31.232 162.275,31.232 166.609,35.566 169.41,35.566 174.303,40.458 174.303,41.906 181.574,49.178 181.574,59.348 177.787,63.135 177.787,64.748 ccw(c177.284,64.748) v1(177.64,65.104)
SATA_2_TXA+_C: C23.1 J27.2 | length 3.5
  L1-TOP w0.107: J27.2@177.315,69.45 177.315,68.708 177.79,68.233 177.79,66.631 C23.1@177.437,66.278
SATA_2_TXA-: C25.2 MC3.8 | length 75.6
  L4-SIG w0.107: v1(135.164,25.212) 135.292,25.34 136.175,25.34 137.206,26.371 141.502,26.371 142.127,25.747 143.145,25.747 146.406,29.007 151.024,29.007 151.483,29.466 156.002,29.466 157.447,30.912 162.408,30.912 166.742,35.246 169.543,35.246 174.623,40.326 174.623,41.774 181.894,49.045 181.894,59.481 178.107,63.267 178.107,64.748 cw(c178.611,64.748) v1(178.255,65.104)
SATA_2_TXA-_C: C25.1 J27.3 | length 3.5
  L1-TOP w0.107: C25.1@178.458,66.278 178.11,66.626 178.11,68.243 178.585,68.718 J27.3@178.585,69.45
SATA_2_TXB+: C29.2 MC3.5 | length 74.4
  L4-SIG w0.107: v1(141.344,25.789) 141.288,25.732 cw(c141.115,25.906) 141.115,25.66 140.637,25.66 140.358,25.382 140.358,24.797 140.704,24.451 142.368,24.451 142.789,24.873 144.565,24.873 146.311,26.619 157.443,26.619 160.212,29.388 167.266,29.388 177.839,39.96 178.949,39.96 179.941,40.953 179.941,44.609 183.294,47.961 183.294,60.438 181.915,61.818 181.915,64.754 cw(c182.409,64.754) v1(182.06,65.104)
SATA_2_TXB+_C: C29.1 J27.6 | length 3.5
  L1-TOP w0.107: C29.1@182.263,66.278 181.92,66.62 181.92,68.243 182.395,68.718 J27.6@182.395,69.45
SATA_2_TXB-: C27.2 MC3.7 | length 72.8
  L4-SIG w0.107: v1(141.344,25.212) 141.288,25.269 ccw(c141.115,25.095) 141.115,25.34 140.769,25.34 140.678,25.25 140.678,24.93 140.837,24.771 142.235,24.771 142.657,25.193 144.432,25.193 146.178,26.939 157.31,26.939 160.079,29.708 167.134,29.708 177.706,40.28 178.816,40.28 179.621,41.086 179.621,44.741 182.974,48.094 182.974,60.306 181.595,61.685 181.595,64.754 ccw(c181.1,64.754) v1(181.45,65.104)
SATA_2_TXB-_C: C27.1 J27.5 | length 3.5
  L1-TOP w0.107: J27.5@181.125,69.45 181.125,68.708 181.6,68.233 181.6,66.631 C27.1@181.247,66.278
SMA_REFCLKN: J25.1 MC3.20 | length 93.1
  L4-SIG w0.107: v1(135.164,20.712) cw(c135.474,20.403) 135.474,20.84 138.285,20.84 143.495,15.631 152.237,15.631 153.482,14.387 173.584,14.387 174.33,13.64 196.063,13.64 197.881,11.821 200.318,11.821 210.337,1.803 210.337,0.311 209.997,-0.029 J25.1@201.994,-0.029
SMA_REFCLKP: J24.1 MC3.18 | length 93.6
  L4-SIG w0.107: v1(135.164,21.288) ccw(c135.474,21.598) 135.474,21.16 138.418,21.16 143.627,15.951 152.37,15.951 153.615,14.707 173.716,14.707 174.463,13.96 196.195,13.96 198.014,12.141 200.451,12.141 210.657,1.935 210.657,0.311 210.968,0 J24.1@219,0
SUPPLY_1_CE: R15.1 U3.23 | length 5.2
  L1-TOP w0.203: v1(56.803,56.204) 57.042,55.964 U3.23@57.042,55.49
  L5-SIG w0.127: v1(56.803,56.204) 58.044,56.204 58.514,56.674 58.514,58.484 58.972,58.942 v1(59.022,58.942)
TXN0: C17.2 MC3.52 | length 103.5
  L5-SIG w0.107: v1(135.164,3.712) cw(c135.474,3.403) 135.474,3.84 139.431,3.84 140.943,2.328 141.263,2.328 143.022,0.569 189.857,0.569 194.755,5.467 224.173,5.467 228.829,0.811 232.997,0.811 cw(c232.997,0.356) v1(233.319,0.678)
TXN1: C21.2 MC3.48 | length 112
  L5-SIG w0.107: v1(135.164,5.212) cw(c135.474,4.903) 135.474,5.34 141.472,5.34 142.401,4.411 147.027,4.411 147.95,5.334 158.503,5.334 178.702,25.533 220.007,25.533 231.26,36.786 232.997,36.786 cw(c232.997,36.33) v1(233.319,36.652)
TXN2: C9.2 MC3.16 | length 84.9
  L4-SIG w0.107: v1(135.164,22.212) cw(c135.474,21.903) 135.474,22.34 139.126,22.34 141.238,20.229 143.098,20.229 145.581,17.746 152.89,17.746 153.474,17.161 192.479,17.161 197.066,21.749 209.01,21.749 210.333,20.426 210.333,17.989 210.333,17.913 210.333,17.662 cw(c210.198,17.662) 210.198,17.527 210.095,17.527 ccw(c210.095,17.392) 209.96,17.392 209.96,17.276 ccw(c210.095,17.276) 210.095,17.141 210.198,17.141 cw(c210.198,17.006) 210.333,17.006 210.333,16.948 210.333,16.175 cw(c209.878,16.175) v1(210.2,15.853)
TXN3: C13.2 MC3.12 | length 90.2
  L4-SIG w0.107: v1(135.164,23.712) cw(c135.474,23.403) 135.474,23.84 139.821,23.84 140.243,23.419 141.858,23.419 142.324,22.953 143.796,22.953 144.685,22.064 177.646,22.064 196.965,41.383 201.715,41.383 207.305,46.973 207.336,47.005 207.514,47.182 cw(c207.609,47.087) 207.705,47.182 207.779,47.108 ccw(c207.875,47.203) 207.97,47.108 208.052,47.19 ccw(c207.957,47.285) 208.052,47.381 207.978,47.455 cw(c208.074,47.551) 207.978,47.646 208.019,47.687 208.857,48.525 208.857,50.288 209.375,50.806 210.003,50.806 210.333,50.476 210.333,50.126 cw(c209.878,50.126) v1(210.2,49.803)
TXP0: C15.2 MC3.50 | length 103.5
  L5-SIG w0.107: v1(135.164,4.288) ccw(c135.474,4.598) 135.474,4.16 139.563,4.16 141.076,2.648 141.396,2.648 143.154,0.889 189.724,0.889 194.622,5.787 224.305,5.787 228.961,1.131 232.997,1.131 ccw(c232.997,1.587) v1(233.319,1.265)
TXP1: C19.2 MC3.46 | length 112
  L5-SIG w0.107: v1(135.164,5.788) ccw(c135.474,6.098) 135.474,5.66 141.604,5.66 142.534,4.731 146.894,4.731 147.818,5.654 158.37,5.654 178.57,25.853 219.875,25.853 231.127,37.106 232.997,37.106 ccw(c232.997,37.562) v1(233.319,37.239)
TXP2: C7.2 MC3.14 | length 84.9
  L4-SIG w0.107: v1(135.164,22.788) ccw(c135.474,23.098) 135.474,22.66 139.259,22.66 141.37,20.549 143.231,20.549 145.714,18.066 153.023,18.066 153.607,17.481 192.347,17.481 196.934,22.069 209.143,22.069 210.654,20.558 210.654,16.175 ccw(c211.109,16.175) v1(210.787,15.853)
TXP3: C11.2 MC3.10 | length 90.3
  L4-SIG w0.107: v1(135.164,24.288) ccw(c135.474,24.598) 135.474,24.16 139.954,24.16 140.376,23.739 141.99,23.739 142.456,23.273 143.929,23.273 144.818,22.384 177.513,22.384 196.832,41.703 201.582,41.703 208.537,48.657 208.537,50.421 209.242,51.126 210.135,51.126 210.654,50.608 210.654,50.126 ccw(c211.109,50.126) v1(210.787,49.803)
VCCBATT: MC2.6 TP12.1 | length 14.3
  L1-TOP w0.279: MC2.6@75.75,-39.59 75.75,-47.634 77.997,-49.88 TP12.1@77.997,-53
VDDD: C32.2 R14.2 R15.2 R31.2 U3.20 | length 45.8
  L1-TOP w0.203: C32.2@58.022,57.674 C32.2@58.022,57.624 58.022,56.991 58.061,56.953 v1(58.082,56.953) 58.542,56.493 U3.20@58.542,55.49
  L5-SIG w0.305: v1(17.85,63.346) 18.553,62.643 57.65,62.643 59.022,61.271 v1(59.022,59.942)
  other v1: 56.067,44.871
VIO1: J1.39 J2.39 MC1.174 MC1.176 TP1.1
  other v1: 127.75,32.575 128.25,32.575 127.75,34.245 128.25,34.245 62.401,71.976 109.401,71.976 62.401,72.865 109.401,72.865 62.401,73.754 109.401,73.754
